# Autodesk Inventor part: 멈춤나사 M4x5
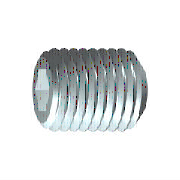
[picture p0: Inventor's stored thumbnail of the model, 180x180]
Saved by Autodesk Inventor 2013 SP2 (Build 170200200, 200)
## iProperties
IsCustomPart: 1
Created: 2012-02
Part Number: 멈춤나사 M4x5
Material: 강철, 연강
Description: 6각 소켓 머리 없는 멈춤 나사
Document SubType Name: Modeling
Standard: KS B 1028
Designer: mduedu
Standards Organization: KS
Language: ko-KR
Size Designation: 납작점M4x5
Categories: <MemberInstance><Categories><Category DisplayName="조임쇠" InternalName="e4da775c-781d-43d5-af7c-5136215cf5a6" Mnemonic="FSTN"><Category DisplayName="볼트" InternalN
Density: 1 g/cm^3
Author: mduedu
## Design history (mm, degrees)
sketch "스케치1"
  geometry: L1 (0, 0)-(1.833, 0); L2 (5, 1.155)-(5, 2); L3 (5, 2)-(0, 2); L4 (5, 1.155)-(2.5, 1.155); L5 (2.5, 1.155)-(1.833, 0); L6 (0, -0.4)-(0, 2.4) reference; L7 (0, 2)-(0, 0)
  constraints: 13 end point, 3 parallel, 1 collinear, 1 perpendicular, 1 point on line
  dimensions: "d0" = 2.5 distance of L2.start L4.end (= INTI); "d1" = 60 deg angle of L5 L1; "d2" = 4 diameter of L3 L1 (= NND); "d3" = 2.3094 diameter of L4 L1 (= 1.1547 x SW); "d5" = 5 distance from line of L2 L3.end (= NLG)
revolve "본체" sketch "스케치1" stored, may be unused: angle "d6" = 90 deg
sketch "스케치2"
  geometry: L1 (-0.577, 1)-(0.577, 1); L2 (0.577, 1)-(1.155, 0); L3 (1.155, 0)-(0.577, -1); L4 (0.577, -1)-(-0.577, -1); L5 (-0.577, -1)-(-1.155, 0); L6 (-1.155, 0)-(-0.577, 1); A1 r 1.155 centre (0, 0) between (-0.577, 1) and (0.577, 1) reference; 2 further points
  constraints: 12 end point, 2 point on circle, 1 coincident, 1 horizontal, 11 other
extrude "슬롯" join sketch "스케치2" taper "d9" = 0 deg; stored distance "d21" = 10
workaxis "Work Axis1"
workplane "Work Plane1"
body "Solid1"
chamfer "모따기1" distance "d7" = 0.42941 (= -0.5 x GD1 + 0.5 x NND); stored, may be unused: angle "d8" = 45 deg (= FAWI), second distance "d29" = 0.42941 (= -0.5 x GD1 + 0.5 x NND)
feature "스레드" dims "d11" = 5 (= NLG), "d12" = 0
chamfer "모따기2" distance "d13" = 0.42941 (= -0.5 x GD1 + 0.5 x NND); stored, may be unused: angle "d14" = 45 deg (= FAWI), second distance "d30" = 0.42941 (= -0.5 x GD1 + 0.5 x NND)
other parameters: "NND" = 4 [user parameter; used in 5 equation terms], "NLG" = 5 [user parameter; used in 2 equation terms], "INTI" = 2.5 [user parameter; used in 1 equation term], "FAWI" = 45 deg [user parameter; used in 2 equation terms], "SW" = 2 [user parameter; used in 2 equation terms], "GD1" = 3.14117 (= THREADDIA - 1.2269 x PTC) [user parameter; used in 4 equation terms], "d4" = 0, "FAWI1" = 45 deg [user parameter], "d15" = 0, "d31" = 0, "GUL" = 0.42941 (= 0.61345 x PTC) [user parameter], "SPD" = 2.5 [user parameter], "TPU" = 14.28571 (computed from PTC) [user parameter], "TOA" = 30 deg [user parameter], "THREADDIA" = 4 [user parameter; used in 1 equation term], "PTC" = 0.7 [user parameter; used in 4 equation terms], "GAL" = 0.42941 (= 0.61345 x PTC) [user parameter], "E0" = 2.31 (= 1.155 x SW) [user parameter]
